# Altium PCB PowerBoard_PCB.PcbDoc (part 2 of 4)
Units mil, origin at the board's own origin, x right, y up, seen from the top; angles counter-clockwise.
Board outline 9251.97 x 3346.46 mil, 6 copper layers (Top Layer, Signal Layer 1, Signal Layer 2, Signal Layer 3, Signal Layer 4, Bottom Layer), stack 65.8 mil thick; 241 components, 145 nets, 894 pads, 120 vias.
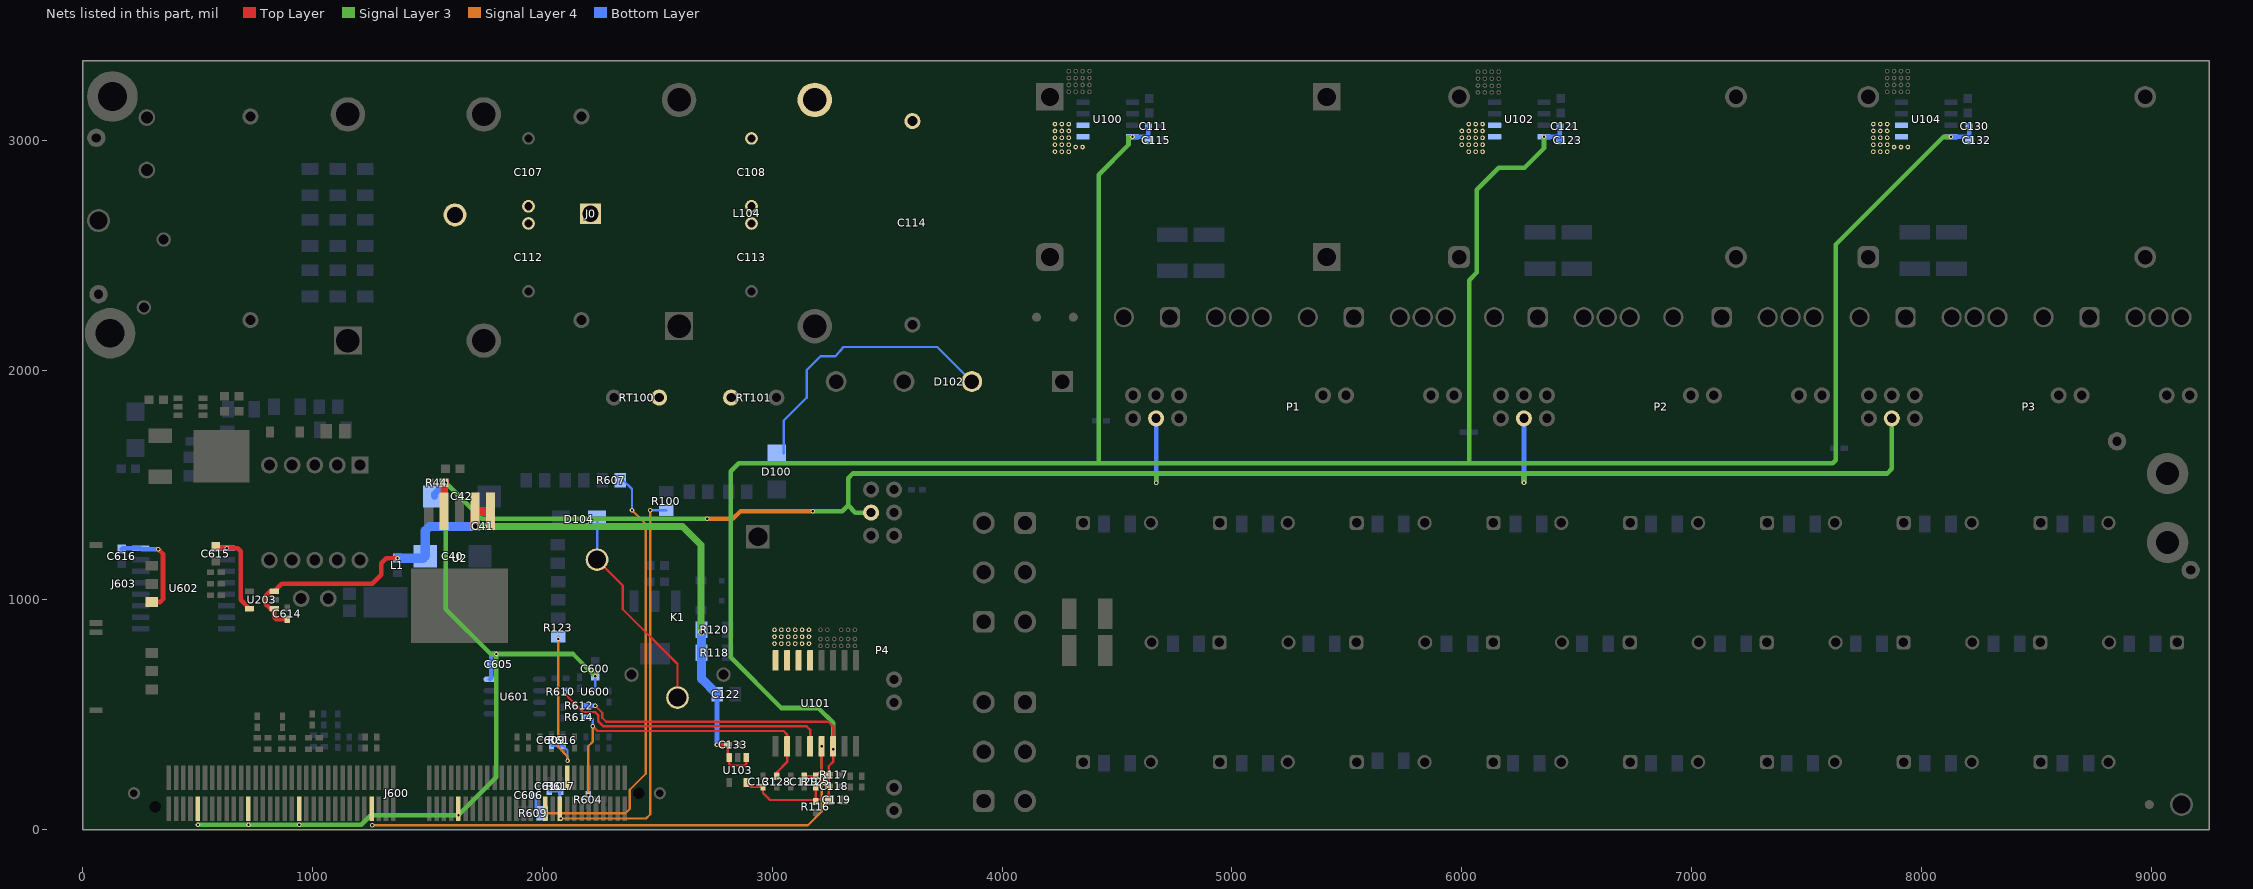
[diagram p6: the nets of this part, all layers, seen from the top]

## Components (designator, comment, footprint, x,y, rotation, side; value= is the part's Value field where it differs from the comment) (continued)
R43 "CRCW08052R70JNEA" 0805_HV 470,1580 r90 bottom value=2.7
R44 "RC0603FR-0720K5L" 0603 1540,1510 r0 top value=20.5k
R45 "RC0603FR-076K19L" 0603 1610,1570 r180 top value=6.19k
R100 "RT0805BRD07361KL" 0805_HV 2540,1430 r90 bottom value=361k
R101 "RT0805BRD07361KL" 0805_HV 2680,1470 r0 bottom value=361k
R102 "RT0805BRD07361KL" 0805_HV 2850,1470 r0 bottom value=361k
R105 "CRCW1206330KJNEA" 1206 1230,2817.09 r90 bottom value=330k
R106 "CRCW1206330KJNEA" 1206 1110,2817.09 r90 bottom value=330k
R107 "CRCW1206330KJNEA" 1206 990,2817.09 r90 bottom value=330k
R108 "CRCW1206330KJNEA" 1206 1230,2597.09 r90 bottom value=330k
R109 "CRCW1206330KJNEA" 1206 1110,2597.09 r90 bottom value=330k
R110 "CRCW1206330KJNEA" 1206 990,2597.09 r90 bottom value=330k
R111 "CRCW1206330KJNEA" 1206 1230,2377.09 r90 bottom value=330k
R112 "CRCW1206330KJNEA" 1206 1110,2377.09 r90 bottom value=330k
R113 "CRCW1206330KJNEA" 1206 990,2377.09 r90 bottom value=330k
R116 "CRCW040210K0FKED" 0402 3190,100 r90 top value=10.0k
R117 "CRCW040212K7FKED" 0402 3270,240 r0 top value=12.7k
R118 "CRCW12066R20JNEA" 1206 2750,770 r180 bottom value=6.2
R119 "RT0805BRD07361KL" 0805_HV 2066.61,1200 r90 bottom value=361k
R120 "CRCW12066R20JNEA" 1206 2750,870 r180 bottom value=6.2
R121 "RT0805BRD07361KL" 0805_HV 2070.05,1040 r90 bottom value=361k
R122 "RC0603FR-0710KL" 0603 2500,1150 r180 bottom value=10.0k
R123 "RT0805BRD07361KL" 0805_HV 2070,880 r90 bottom value=361k
R124 "CRCW04025K49FKED" 0402 3340,210 r90 top value=5.49k
R125 "CRCW0402330KJNED" 0402 3190,210 r90 top value=330k
R600 "CRCW04021K40FKED" 0402 2090,378.19 r270 top value=1.40k
R601 "CRCW04022K00FKED" 0402 2161.82,640 r270 bottom value=2.00k
R602 "RT0805BRD07361KL" 0805_HV 1970,1520 r180 bottom value=361k
R603 "CRCW04021K40FKED" 0402 2040,378.19 r270 top value=1.40k
R604 "CRCW040210K0JNED" 0402 2200,130 r90 bottom value=10k
R605 "RT0805BRD07361KL" 0805_HV 2140,1520 r0 bottom value=361k
R606 "CRCW04023K92FKED" 0402 2080,660 r0 bottom value=1.8k
R607 "RT0805BRD07361KL" 0805_HV 2300,1520 r0 bottom value=361k
R608 "CRCW04021K40FKED" 0402 1890,380 r270 top value=1.40k
R609 "CRCW08055K49FKEA" 0805_HV 1960,71.58 r0 bottom value=5.49k
R610 "CRCW04021K00FKED" 0402 2080,600 r180 bottom value=1.00k
R611 "RC0402FR-0733RL" 0402 2190,380 r90 bottom value=33.0
R612 "CRCW040210K0FKED" 0402 2161.82,540 r0 bottom value=10.0k
R613 "ERA-2AEB4871X" 0402 2240,380 r270 bottom value=4.87k
R614 "CRCW04020000Z0ED" 0402 2161.82,490 r0 bottom value=0
R615 "CRCW040210K0FKED" 0402 2090,510 r90 bottom value=10.0k
R616 "CRCW04025K23FKED" 0402 2090,390 r270 bottom value=5.23k
R617 "CRCW04025K23FKED" 0402 2080,190 r270 bottom value=5.23k
R618 "CRCW04024K99FKED" 0402 1000,480 r90 top value=4.99k
R620 "CRCW04024K99FKED" 0402 870,470 r90 top value=4.99k
R621 "CRCW04020000Z0ED" 0402 4430,1780 r180 bottom value=0
R624 "CRCW04024K99FKED" 0402 760,470 r90 top value=4.99k
R625 "CRCW04020000Z0ED" 0402 6030,1730 r180 bottom value=0
R626 "CRCW04020000Z0ED" 0402 7640,1660 r180 bottom value=0
R630 "CRCW04021K40FKED" 0402 1280,380 r270 top value=1.40k
R631 "CRCW04029K31FKED" 0402 1006.35,400 r0 top value=9.31k
R632 "CRCW04029K31FKED" 0402 890,350 r0 top value=9.31k
R633 "CRCW04029K31FKED" 0402 783.62,400 r180 top value=9.31k
R634 "CRCW04020000Z0ED" 0402 3630,1480 r0 bottom value=0
R635 "CRCW04024K99FKED" 0402 1050,480 r90 bottom value=4.99k
R636 "CRCW04029K31FKED" 0402 1028,411.65 r0 bottom value=9.31k
R640 "CRCW04020000Z0ED" 0402 1110,381.65 r270 bottom value=0
R641 "CRCW04020000Z0ED" 0402 1160,380 r270 bottom value=0
R642 "CRCW04020000Z0ED" 0402 1210,380 r90 bottom value=0
R643 "CRCW04020000Z0ED" 0402 1110,480 r270 bottom value=0
R644 "CRCW04020000Z0ED" 0402 580,1120 r0 top value=0
R645 "CRCW04020000Z0ED" 0402 580,1070 r0 top value=0
R646 "CRCW04020000Z0ED" 0402 580,1020 r0 top value=0
RT100 "B59751B0120A070" TDK_B751 2410,1880 r90 top value=50
RT101 "B59751B0120A070" TDK_B751 2920,1880 r270 top value=50
RV100 "S10K275E2" VAR_S10K275E2 310,2420 r90 top
T1 "7508110162" WURTH_7508110162 1010,1380 r270 top
TP100 "5000" Keystone5000 8850,1690 r90 top value=Red
TP101 "5000" Keystone5000 60,3010 r90 top value=Red
TP102 "5001" Keystone5001 9170,1130 r90 top value=Black
TP103 "5001" Keystone5001 70,2330 r90 top value=Black
U1 "UCC28700QDBVRQ1" DBV0006A_N 470,1840 r0 top
U2 "TL1963AQKTTRQ1" KTT0005A_N 1640,1140 r270 top
U100 "ACS722LLCTR-20AB-T" SOIC-8 4460,3090 r0 bottom
U101 "ACS716KLATR-25CB-NL-T" SOIC-16 3190,550 r270 top
U102 "ACS722LLCTR-20AB-T" SOIC-8 6250,3090 r0 bottom
U103 "TLV71333PQDBVRQ1" DBV0005A_N 2850,260 r270 top
U104 "ACS722LLCTR-20AB-T" SOIC-8 8020,3090 r0 bottom
U203 "TLV71333PQDBVRQ1" DBV0005A_N 780,1000 r180 top
U600 "SN74LVC1G3157DRYR" DRY0006A 2230,600 r90 bottom
U601 "OPA2376AIDG4" D0008A_N 1880,580 r180 bottom
U602 "ISO7831DWR" DW0016B_N 440,1050 r180 bottom

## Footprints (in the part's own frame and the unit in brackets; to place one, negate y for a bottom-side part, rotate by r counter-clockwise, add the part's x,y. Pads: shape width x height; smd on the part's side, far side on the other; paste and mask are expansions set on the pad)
0402 [mm] "0402 from SM-752 data"
  rect 0.8x0.6 smd: 1(-0.6,0) 2(0.6,0)
  silkscreen extent -1.22,-0.52 1.22,0.52, body extent -0.55,-0.3 0.55,0.3, height 0.6
0603 [mm] "0603 from SM-752 data"
  rect 1x0.95 smd: 1(-0.8,0) 2(0.8,0)
  silkscreen extent -1.52,-0.69 1.52,0.69, body extent -0.87,-0.47 0.87,0.47, height 1
0805_HV [mil] "0805 with 30mil clearance between pads"
  rect 50x63 smd: 1(-40,0) 2(40,0)
  silkscreen extent -74,-40 74,40, body extent -43,-29 43,29, height 57
1206 [mm] "1206 from SM-752 data"
  rect 1.3x1.85 smd: 1(-1.45,0) 2(1.45,0)
  silkscreen extent -2.4,-1.21 2.4,1.21, body extent -1.7,-0.9 1.7,0.9, height 1.35
1206_180 [mm] "1206_180"
  rect 1.1x1.6 smd: 1(-1.7,0) 2(1.7,0)
  silkscreen extent -0.9,-1 0.9,1, body extent -1.75,-0.95 1.75,0.95, height 1.8
1812 [mm]
  rect 1.6x3.4 smd: 1(-2,0) 2(2,0)
  silkscreen extent -0.8,-1.6 0.8,1.6, body extent -2.4,-1.7 2.4,1.7, height 1.35
7343-30 [mm] "Medium Density based on Kemet T495 dimensions"
  rect 2.55x2.45 smd: 1(-3.025,0) 2(3.025,0)
  silkscreen extent -3.8,-2.25 3.8,2.25, body extent -3.8,-2.3 3.8,2.3, height 3.1
BXW_1450x4500 [mm] "TH, 2-Leads, Dia 14.5mm, Pin Spacing 7.5mm"
  rrect50% 1.575x1.575 hole 1.05: 1(-3.75,0)
  round 1.575 hole 1.05: 2(3.75,0)
  silkscreen extent -7.5,-7.5 7.5,7.5, body extent -7.5,-7.49 7.51,7.49, height 47
controlCARD-120HSEC [mm] "Pads are not numbered according to Samtec datasheet."
  rect 0.5x2.724 smd: 1(-23.357,-1.678) 2(-23.357,1.722) 3(-22.557,-1.678) 4(-22.557,1.722) 5(-21.757,-1.678) 6(-21.757,1.722) 7(-20.957,-1.678) 8(-20.957,1.722) 9(-20.157,-1.678) 10(-20.157,1.722) 11(-19.357,-1.678) 12(-19.357,1.722) 13(-18.557,-1.678) 14(-18.557,1.722) 15(-17.757,-1.678) 16(-17.757,1.722) 17(-16.957,-1.678) 18(-16.957,1.722) 19(-16.157,-1.678) 20(-16.157,1.722) 21(-15.357,-1.678) 22(-15.357,1.722) 23(-14.557,-1.678) 24(-14.557,1.722) 25(-13.757,-1.678) 26(-13.757,1.722) 27(-12.957,-1.678) 28(-12.957,1.722) 29(-12.157,-1.678) 30(-12.157,1.722) 31(-11.357,-1.678) 32(-11.357,1.722) 33(-10.557,-1.678) 34(-10.557,1.722) 35(-9.757,-1.678) 36(-9.757,1.722) 37(-8.957,-1.678) 38(-8.957,1.722) 39(-8.157,-1.678) 40(-8.157,1.722) 41(-7.357,-1.678) 42(-7.357,1.722) 43(-6.557,-1.678) 44(-6.557,1.722) 45(-5.757,-1.678) 46(-5.757,1.722) 47(-4.957,-1.678) 48(-4.957,1.722) 49(-4.157,-1.678) 50(-4.157,1.722) 51(-3.357,-1.678) 52(-3.357,1.722) 53(-2.557,-1.678) 54(-2.557,1.722) 55(-1.757,-1.678) 56(-1.757,1.722) 57(2.243,-1.678) 58(2.243,1.722) 59(3.043,-1.678) 60(3.043,1.722) 61(3.843,-1.678) 62(3.843,1.722) 63(4.643,-1.678) 64(4.643,1.722) 65(5.443,-1.678) 66(5.443,1.722) 67(6.243,-1.678) 68(6.243,1.722) 69(7.043,-1.678) 70(7.043,1.722) 71(7.843,-1.678) 72(7.843,1.722) 73(8.643,-1.678) 74(8.643,1.722) 75(9.443,-1.678) 76(9.443,1.722) 77(10.243,-1.678) 78(10.243,1.722) 79(11.043,-1.678) 80(11.043,1.722) 81(11.843,-1.678) 82(11.843,1.722) 83(12.643,-1.678) 84(12.643,1.722) 85(13.443,-1.678) 86(13.443,1.722) 87(14.243,-1.678) 88(14.243,1.722) 89(15.043,-1.678) 90(15.043,1.722) 91(15.843,-1.678) 92(15.843,1.722) 93(16.643,-1.678) 94(16.643,1.722) 95(17.443,-1.678) 96(17.443,1.722) 97(18.243,-1.678) 98(18.243,1.722) 99(19.043,-1.678) 100(19.043,1.722) 101(19.843,-1.678) 102(19.843,1.722) 103(20.643,-1.678) 104(20.643,1.722) 105(21.443,-1.678) 106(21.443,1.722) 107(22.243,-1.678) 108(22.243,1.722) 109(23.043,-1.678) 110(23.043,1.722) 111(23.843,-1.678) 112(23.843,1.722) 113(24.643,-1.678) 114(24.643,1.722) 115(25.443,-1.678) 116(25.443,1.722) 117(26.243,-1.678) 118(26.243,1.722) 119(27.043,-1.678) 120(27.043,1.722)
  round 0.025 hole 1.27 unplated mask+0.876: 181(-24.857,0.022) 182(28.543,1.522)
  round 1.348 hole 0.84: 185(-27.207,0.022) 186(30.893,0.022)
  silkscreen extent -32.11,-3.86 35.8,3.9, body extent -31.75,-3.48 35.3,3.52, height 12.35
D0008A_N [mm] "SOIC, 8-Leads, Body 4.9x3.9mm, Pitch 1.27mm, IPC Medium Density"
  oval 1.45x0.6 smd: 1(-2.725,1.905) 2(-2.725,0.635) 3(-2.725,-0.635) 4(-2.725,-1.905) 5(2.725,-1.905) 6(2.725,-0.635) 7(2.725,0.635) 8(2.725,1.905)
  silkscreen extent -3.3,-2.5 0.9,2.5, body extent -3,-2.45 3,2.45, height 1.63
DBV0005A_N [mm] "SOT23, 5-Leads, Body 2.9x1.6mm, Pitch 0.95mm, Lead Span 2.8mm, IPC Medium Density"
  rrect17% 1x0.6 smd: 1(-1.375,0.95) 2(-1.375,0) 3(-1.375,-0.95) 4(1.375,-0.95) 5(1.375,0.95)
  silkscreen extent -1.63,-1.55 0.38,1.55, body extent -1.42,-1.46 1.42,1.46, height 1.09
DBV0006A_N [mm] "SOT23, 6-Leads, Body 2.9x1.6mm, Pitch 0.95mm, Lead Span 2.8mm, IPC Medium Density"
  rrect17% 1x0.6 smd: 1(-1.375,0.95) 2(-1.375,0) 3(-1.375,-0.95) 4(1.375,-0.95) 5(1.375,0) 6(1.375,0.95)
  silkscreen extent -1.68,-1.55 0.5,1.55, body extent -1.42,-1.46 1.42,1.46, height 1.12
DPAK [mm] "D-PAK, 3-Pads, Body 6.22x6.73mm (max), TO-252AA using nominal STEP model"
  rrect6% 2.6x1.6 smd: 1(-3.4,2.28) 3(-3.4,-2.28)
  rrect2% 6.2x5.8 smd paste-2.9: 4(3.4,0)
  silkscreen extent -4.5,-3.3 4.7,3.28, body extent -3.86,-3.29 5.84,3.29, height 2.48
Driver [mil]
  round 70 hole 40: 1(-200,-100) 2(-100,-100) 3(0,-100) 4(-200,0) 5(-100,0) 6(0,0) 7(626,0) 8(726,0) 9(1096,0) 10(1196,0)
  silkscreen extent -305,-250 1280,248, body extent -299,-249 1276,244, height 1600
DRY0006A [mm] "PSON, 6-Leads, Body 1x1.45mm, Pitch 0.5mm, TI Recommended"
  rect 0.35x0.2 smd: 1(-0.275,0.5)
  rect 0.3x0.2 smd: 2(-0.3,0) 3(-0.3,-0.5) 4(0.3,-0.5) 5(0.3,0) 6(0.3,0.5)
  silkscreen extent -0.5,-0.85 0.2,0.85, body extent -0.53,-0.75 0.53,0.75, height 0.61
DW0016B_N [mm] "SOIC, 16-Leads, Body 10.5x7.6mm, Pitch 1.27mm, IPC Medium Density"
  rrect17% 1.9x0.6 smd: 1(-4.75,4.445) 2(-4.75,3.175) 3(-4.75,1.905) 4(-4.75,0.635) 5(-4.75,-0.635) 6(-4.75,-1.905) 7(-4.75,-3.175) 8(-4.75,-4.445) 9(4.75,-4.445) 10(4.75,-3.175) 11(4.75,-1.905) 12(4.75,-0.635) 13(4.75,0.635) 14(4.75,1.905) 15(4.75,3.175) 16(4.75,4.445)
  silkscreen extent -5.6,-5.25 3.4,5.25, body extent -5.17,-5.15 5.17,5.15, height 2.59
E_900x700x900 [mm] "TH, 2- Leads, Body 9x7mm, Pin Spacing 7.5mm"
  round 1.4 hole 0.9: 1(-3.75,0) 2(3.75,0)
  silkscreen extent -4.5,-3.5 4.5,3.5, body extent -4.5,-3.5 4.5,3.5, height 12
Fiducial10-20 [mm]
  round 1 smd mask+0.5: 1(0,0)
  Top Layer keep-out circle w1.178: c0,0 r0.5
FUSE_0325_Vertical [mm] "TH, 2-Leads, Dia 6.985mm, Verical, Pin Spacing 5.8025mm"
  round 1.85 hole 1.35: 1(0,0) 2(-5.803,0)
  silkscreen extent -3.64,-3.64 3.64,3.64, body extent -6.34,-3.64 3.64,3.64, height 37.62
G184014LF#1 [mm] "TH, 4-Leads, Dia 42.5mm"
  rrect50% 3.048x3.048 hole 2: 1(-8.85,15.3)
  rect 3.048x3.048 hole 2: 2(8.85,15.3) 3(8.85,-15.3) 4(-8.85,-15.3)
  body extent -11.8,-21.25 11.84,21.25, height 44.5
G184014LF#2 [mm] "TH, 4-Leads, Dia 42.5mm"
  rrect50% 2.4x2.4 hole 1.6: 1(-8.85,15.3)
  round 2.4 hole 1.6: 2(8.85,15.3) 3(8.85,-15.3) 4(-8.85,-15.3)
  body extent -11.8,-21.25 11.84,21.25, height 44.5
GBJ [mm] "Micro Commercial Components"
  rect 2.3x2.3 hole 1.6: 1(-12.5,0)
  round 2.3 hole 1.6: 2(-2.5,0) 3(5,0) 4(12.5,0)
  silkscreen extent -15.3,-1.8 15,3.1, body extent -15.25,-1.75 15.05,3.05, height 24.3
Hirose_DF59-3S-2V_51 [mm] "Receptacle, 2mm, 3x1, SMT"
  rect 1.1x1.4 smd: 1(-2,7.9) 2(0,7.9) 3(2,7.9)
  rect 0.65x1.4 smd: MP1(-4.31,1.75) MP2(4.31,1.75)
  silkscreen extent -4.6,2.75 4.6,8.25, body extent -4.6,0.35 4.6,8.3, height 2.3
IEC_HighVoltage_Small [mil]
  silkscreen extent -107,-88 107,97
Keystone5000 [mil] "For Keystone 500x miniature loop terminals"
  round 80 hole 40: 1(0,0)
  silkscreen extent -52,-52 52,52, body extent -49,-49 49,49, height 182
Keystone5001 [mil] "For Keystone 500x miniature loop terminals"
  round 80 hole 40: 1(0,0)
  silkscreen extent -52,-52 52,52, body extent -49,-49 49,49, height 182
KTT0005A_N [mm] "D2-PAK, 6-Leads, Body 8.9x10.2mm, Pitch 1.7mm, Lead Span 15.2mm, IPC Medium Density"
  rrect10% 4.15x1 smd: 1(-6.25,3.4) 2(-6.25,1.7) 3(-6.25,0) 4(-6.25,-1.7) 5(-6.25,-3.4)
  rrect1% 8.2x10.75 smd: 6(4.2,0)
  silkscreen extent -6.42,-5.35 -0.3,5.35, body extent -7.63,-5.08 7.63,5.08, height 4.83
Pb-Free_Overlay_Small [mil]
  silkscreen extent -46,-46 46,46
PIN1 [mil] "Connector; Plug"
  rect 90x90 hole 70: 1(0,0)
  silkscreen extent -55,-55 55,86
POWERDI5 [mm] "Diodes Inc recommended land pattern, ap02001.pdf rev 60"
  rect 1.4x1.39 smd: 1(-1.991,0.92) 2(-1.991,-0.92)
  rect 4.86x3.36 smd: 3(1.991,0)
  silkscreen extent -1.7,-2.1 3.8,2.1, body extent -2.27,-2.02 4.33,2.03, height 1.17
Relay_T90S1 [mm] "TH, 5-Leads, Body 27.43x32.26mm"
  rect 2.6x2.6 hole 2.06: 1(8.335,5.97)
  round 2.5 hole 1.98: 2(-9.445,3.43) 3(-0.555,-11.81)
  round 1.6 hole 1.09: 4(-5.635,-9.27) 5(4.525,-9.27)
  silkscreen extent -13.71,-16.13 14.53,16.13, body extent -13.71,-16.13 13.71,16.13, height 20.4
SMA [mm] "Molded Diode, 2-Leads, Body 4.3x2.6mm, IPC Medium Density, based on OnSemi component dimensions and land pattern"
  rect 2x2 smd: 1(-2,0) 2(2,0)
  silkscreen extent -3.66,-1.57 2.79,1.57, body extent -2.6,-1.3 2.6,1.3, height 2.42
SOD-123 [mm] "On Semi recommended land pattern"
  rect 0.915x1.22 smd: 1(-1.637,0) 2(1.637,0)
  silkscreen extent -2.74,-1.17 2.03,1.17, body extent -1.93,-0.9 1.93,0.9, height 1.35
SOD-323 [mm] "NXP recommended land pattern"
  rect 0.6x0.6 smd paste-0.05: 1(-1.1,0) 2(1.1,0)
  silkscreen extent -2.06,-0.86 1.53,0.86, body extent -1.3,-0.67 1.3,0.68, height 1.1
SOIC-8 [mm] "duplicate of SO-8.  SOIC, 8-Leads, Body 5.0x4.0mm (max), Pitch 1.27mm, IPC Medium Density"
  rrect17% 1.45x0.6 smd: 1(-2.725,1.905) 2(-2.725,0.635) 3(-2.725,-0.635) 4(-2.725,-1.905) 5(2.725,-1.905) 6(2.725,-0.635) 7(2.725,0.635) 8(2.725,1.905)
  silkscreen extent -3.5,-2.5 0.9,2.5, body extent -3,-2.45 3,2.45, height 1.63
SOIC-16 [mm] "SOIC, 16-Leads, Body 10.3x7.5mm, Pitch 1.27mm"
  rrect15% 2.25x0.65 smd: 1(-4.75,4.445) 2(-4.75,3.175) 3(-4.75,1.905) 4(-4.75,0.635) 5(-4.75,-0.635) 6(-4.75,-1.905) 7(-4.75,-3.175) 8(-4.75,-4.445) 9(4.75,-4.445) 10(4.75,-3.175) 11(4.75,-1.905) 12(4.75,-0.635) 13(4.75,0.635) 14(4.75,1.905) 15(4.75,3.175) 16(4.75,4.445)
  silkscreen extent -4.87,-5.25 3.8,5.45, body extent -5.32,-5.25 5.32,5.25, height 2.64
SOT-223 [mm] "SOT223/SC73, 4-Leads, Body 6.5x3.5mm, Pitch 2.3mm, Lead Span 7mm, IPC Medium Density"
  rrect10% 2.4x1 smd: 1(-2.9,2.3) 2(-2.9,0) 3(-2.9,-2.3)
  rrect4% 2.4x3.3 smd: 4(2.9,0)
  silkscreen extent -3.32,-3.35 1.4,3.35, body extent -3.5,-3.25 3.5,3.25, height 1.62
TDK_B751 [mil] "TH, 2-Leads, Dia 12.5mm, Pin Spacing 5mm"
  round 70 hole 40: 1(0,98.43) 2(0,-98.43)
  silkscreen extent -138,-246 138,246, body extent -137,-244 137,246, height 649
TO-247 [mil] "Standard TO-247"
  rrect50% 95x95 hole 62: 1(-215,0)
  round 95 / inner round 74.8 / far side round 96 hole 62: 2(0,0) 3(215,0)
  silkscreen extent -318,-124 318,81, body extent -318,-124 318,81, height 1007
TO-247-4 [mm] "FM, 4-Leads, Body 15.94x5.02mm, Pitch 2.54mm"
  rrect50% 2.24x2.24 hole 1.7: 1(-5.08,0)
  round 2.24 hole 1.7: 2(0,0) 3(2.54,0) 4(5.08,0)
  silkscreen extent -8.07,-2.49 8.07,2.72, body extent -8.07,-2.49 8.07,2.72, height 27.97
VAR_S10K275E2 [mm] "EPCOS"
  round 1.6 hole 1.1: 1(-3.75,1.1) 2(3.75,-1.1)
  silkscreen extent -6,-2.7 6,2.7, body extent -5.98,-2.7 5.98,2.7, height 14.99
WCAP-FTX2_2600x1500x2500 [mil] "TH, 2-Leads, Body 26x15mm, Pin Spacing 22.5mm"
  round 70 hole 43.31: 1(-442.91,0) 2(442.91,0)
  silkscreen extent -512,-295 512,295, body extent -512,-295 512,295, height 984
WE-CMBNC_XL [mm] "TH, 4-Leads, Body 37x23mm"
  rect 3.1x3.1 hole 2.6: 1(-7.5,-12.5)
  round 3.81 hole 2.6: 2(-7.5,12.5) 3(7.5,12.5) 4(7.5,-12.5)
  silkscreen extent -10.3,-16.17 10.3,16.17, body extent -10.3,-16.17 10.3,16.17, height 30.09
WURTH_7508110162 [mm] "WURTH"
  rect 1.85x1.85 hole 1.191: 1(-5.25,5)
  round 1.85 hole 1.191: 2(-5.25,2.5) 3(-5.25,0) 4(-5.25,-2.5) 5(-5.25,-5) 6(5.25,-5) 7(5.25,-2.5) 8(5.25,0) 9(5.25,2.5) 10(5.25,5) A(9.5,1.5) B(9.5,-1.5)
  silkscreen extent -7,-6.8 7,7, body extent -6.98,-6.95 7.04,6.85, height 7

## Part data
C1 C2 C3 C4 C5 C6 C7 C8 C9 C10 C11 C12 C13 C14 C15 C16 C17 C18 C19 C20 C21 C22 C23 C24: library part CMP-0077904-1, "CAP, AL, 150 µF, 350 V, +/- 20%, TH", Cap_Case=14.5x45mm, Manufacturer=Rubycon, Supplier Part Number 1=93Y0837, Tolerance_%=20%, Value2=350V, ValueDisplayed=150µF
C27 C28 C29 C30 C31 C32 C33 C34: "CAP, CERM, 0.1µF, 1kV,+/- 10%, X7R, 1812", Cap_Case=1812, Manufacturer=KEMET, PartNumber=C1812C104KDRAC7800, TempCo=X7R, Tolerance_%=10, Value2=1000V, ValueDisplayed=0.1µF
C35: "CAP, CERM, 10 µF, 25 V,+/- 10%, X7R, 1206", Cap_Case=1206, Manufacturer=MuRata, Supplier Part Number 1=81-GRM31CR71E106KA12, TempCo=X7R, Tolerance_%=10, Value2=25V, ValueDisplayed=10µF
C36: library part CMP-0064943-2, "CAP, CERM, 1000 pF, 250 V,+/- 10%, X7R, 0805", Cap_Case=0805, Manufacturer=TDK, Supplier Part Number 1=445-2277-1-ND, TempCo=X7R, Tolerance_%=10%, Value1=Unknown, Value2=250V, ValueDisplayed=1000pF
C37: "CAP, CERM, 68pF, 50V, +/-5%, C0G/NP0, 0603", Cap_Case=0603, Manufacturer=AVX, Supplier Part Number 1=478-1173-1-ND, TempCo=C0G/NP0, Tolerance_%=5, Value1="0.144 ohm", Value2=50V, ValueDisplayed=68pF
C38 C41 C115 C119 C123 C132: "CAP, CERM, 1uF, 6.3V, +/-10%, X5R, 0603", Cap_Case=0603, Manufacturer=MuRata, Supplier Part Number 1=81-GRM185R60J105KE26, TempCo=X5R, Tolerance_%=10, Value1=Unknown, Value2=6.3V, ValueDisplayed=1µF
C39 C40 C42: "CAP, Tantalum Polymer, 220 µF, 10 V,+/- 20%, 0.025 ohm, 7343-30 SMD", Cap_Case=7343-30, Manufacturer=Panasonic, Supplier Part Number 1=P16451CT-ND, Tolerance_%=20, Value1="0.025 ohm", Value2=10V, ValueDisplayed=220µF
C107 C108 C112 C113: "CAP, CERM, 2200 pF, 300 V, +/- 20%, E, TH, 2- Leads, Body 9x7mm, Pin Spacing 7.5mm", Cap_Case=9x7x9mm, Manufacturer=MuRata, Supplier Part Number 1=DE6E3KJ222MN3A-ND, TempCo=E, Tolerance_%=20, Value1=Unknown, Value2=300V, ValueDisplayed=2200pF
C109 C110 C114: "CAP, Film, 2.2 µF, 275 V, +/- 10%, TH", Cap_Case=26x15x25mm, Manufacturer="Wurth Elektronik", Supplier Part Number 1=732-5914-ND, Tolerance_%=10, Value1=Unknown, Value2=275V, ValueDisplayed=2.2µF
C111 C118 C121 C124 C130 C131 C133 C614: "CAP, CERM, 0.1uF, 6.3V, +/-10%, X7R, 0402", Cap_Case=0402, Manufacturer=MuRata, Supplier Part Number 1=GRM155R70J104KA01D-ND, TempCo=X7R, Tolerance_%=10, Value1=Unknown, Value2=6.3V, ValueDisplayed=0.1uF
C116 C125 C134: "CAP, CERM, 1000 pF, 50 V, +/- 10%, C0G/NP0, 0603", Cap_Case=0603, Manufacturer=AVX, Supplier Part Number 1=478-3718-1-ND, TempCo=C0G/NP0, Tolerance_%=10, Value1="0.048 ohm", Value2=50V, ValueDisplayed=1000pF
C120: "CAP, CERM, 1000pF, 16V, +/-10%, X7R, 0603", Cap_Case=0603, Manufacturer=MuRata, Supplier Part Number 1=GRM188R71C102KA01D-ND, TempCo=X7R, Tolerance_%=10, Value1=Unknown, Value2=16V, ValueDisplayed=1000pF
C122: "CAP, CERM, 10 µF, 16 V,+/- 10%, X5R, 0805", Cap_Case=0805, Manufacturer=AVX, Supplier Part Number 1=478-5165-1-ND, TempCo=X5R, Tolerance_%=10, Value2=16V, ValueDisplayed=10µF
C127 C128: "CAP, CERM, 1000pF, 6.3V, +/-10%, X5R, 0402", Cap_Case=0402, Manufacturer=MuRata, Supplier Part Number 1=GRM155R60J102KA01D-ND, TempCo=X5R, Tolerance_%=10, Value1=Unknown, Value2=6.3V, ValueDisplayed=1000pF
C129: "CAP, CERM, 0.022uF, 6.3V, +/-10%, X7R, 0402", Cap_Case=0402, Manufacturer=MuRata, Supplier Part Number 1=GRM155R70J223KA01D-ND, TempCo=X7R, Tolerance_%=10, Value1=Unknown, Value2=6.3V, ValueDisplayed=0.022uF
C600 C605 C615 C616: "CAP, CERM, 1uF, 25V, +/-10%, X7R, 0603", Cap_Case=0603, Manufacturer=TDK, Supplier Part Number 1=445-5956-1-ND, TempCo=X7R, Tolerance_%=10, Value1=Unknown, Value2=25V, ValueDisplayed=1uF
C601 C604 C607 C611 C612 C613 C617 C618: "CAP, CERM, 0.01uF, 6.3V, +/-10%, X7R, 0402", Cap_Case=0402, Manufacturer=MuRata, Supplier Part Number 1=GRM155R70J103KA01D-ND, TempCo=X7R, Tolerance_%=10, Value1=Unknown, Value2=6.3V, ValueDisplayed=0.01uF
C602: "CAP, CERM, 0.1 µF, 16 V, +/- 10%, X7R, 0402", Cap_Case=0402, Manufacturer=MuRata, Supplier Part Number 1=490-4759-2-ND, TempCo=X7R, Tolerance_%=10, Value1=Unknown, Value2=16V, ValueDisplayed=0.1µF
C603: "CAP, CERM, 0.1uF, 6.3V, +/-10%, X5R, 0402", Cap_Case=0402, Manufacturer=MuRata, Supplier Part Number 1=GRM155R60J104KA01D-ND, TempCo=X5R, Tolerance_%=10, Value1=Unknown, Value2=6.3V, ValueDisplayed=0.1µF
C606 C609 C610: "CAP, CERM, 470 pF, 50 V,+/- 5%, C0G/NP0, 0402", Cap_Case=0402, Manufacturer=MuRata, Supplier Part Number 1=490-1297-1-ND, TempCo=C0G/NP0, Tolerance_%=5, Value2=50V, ValueDisplayed=470pF
C608: library part C1005X5R1A473K050BA, "CAP, CERM, 0.047 µF, 10 V, +/- 10%, X5R, 0402", Cap_Case=0402, Manufacturer=TDK, Supplier Part Number 1=445-4980-1-ND, TempCo=X5R, Tolerance_%=10, Value1=Unknown, Value2=10V, ValueDisplayed=0.047µF
D1: "Diode, Ultrafast, 200 V, 1 A, SMA", Manufacturer="Diodes Inc.", Supplier Part Number 1=ES1D-FDICT-ND, Value1=1A, Value2=0.92V
D2: library part US1M-13-F, "Diode, Ultrafast, 800V, 1A, SMA", Manufacturer="Diodes Inc.", Supplier Part Number 1=US1M-FDICT-ND, Value1=1A, Value2=800V
D3: library part CMP-0077048-1, "Diode, Schottky, 100 V, 5 A, PowerDI5", Manufacturer="Diodes Inc.", Supplier Part Number 1=PDS5100DICT-ND, Value1=5A, Value2=0.79V
D100 D104: "Diode, Fast Rectifier, 800 V, 1 A, SMA", Manufacturer="Diodes Inc.", Supplier Part Number 1=US1K-FDICT-ND, Value1=1A, Value2=1.7V
D102: "Diode, Switching-Bridge, 1000 V, 25 A, TH", Manufacturer="Diodes Inc.", Supplier Part Number 1=GBJ2510-FDI-ND, Value1=25A, Value2=1.05V
D105: "Diode, Zener, 5.1 V, 500 mW, SOD-123", Manufacturer="ON Semiconductor", Power_W=0.5, Supplier Part Number 1=MMSZ4689T1GOSCT-ND, Value1=0.5W
D106: "Diode, Schottky, 40 V, 0.75 A, AEC-Q101, SOD-323", Manufacturer="Infineon Technologies", Supplier Part Number 1=BAT165E6327HTSA1CT-ND, Value1=0.75A, Value2=0.74V
F100: library part CMP-0003448-2, "Fuse, 40 A, 250 VAC, 150 VDC, TH", Irating_A=40A, Manufacturer=Littelfuse, Supplier Part Number 1=F3336-ND
FID1 FID2 FID3: "Fiducial mark.  There is nothing to buy or mount.", Manufacturer=N/A
J600: library part controlCARD-120HSEC, "C2000 controlCARD-120HSEC connector, SMT", Manufacturer=Samtec
J602 J603: "Receptacle, 2mm, 3x1, Gold, Natural, SMT", Color=Natural, Current_A=3, Manufacturer="Hirose Electric Co. Ltd.", Supplier Part Number 1=H11965CT-ND, Voltage_V=230
K1: "Relay, SPST-NO (1 Form A), 30 A, 5 V, TH", Coil Current_A=0.185, Coil Power_W=0.9, Coil Resistance_ohm=27, Coil Voltage_VDC=5, Contact Rating_A=30, Manufacturer="TE Connectivity", Supplier Part Number 1=PB109-ND, Turn Off Voltage (Min)_VDC=0.5, Turn On Voltage (Max)_VDC=3.75
L1: "Ferrite Bead, 15 ohm @ 100 MHz, 1.5 A, 0603", Manufacturer=TDK, Supplier Part Number 1=445-2180-1-ND, Value1="0.05 ohm", Value2=1.5A, ValueDisplayed="15 ohm"
L100 L101 L102: library part CMP-0082528-1, "Inductor, Toroid, 260 µH, 0.038 ohm, TH", Manufacturer="GCI Technologies", Value1="0.038 ohm", Value2=A, ValueDisplayed=260µH
L103 L104: "CMC 2.5MH 25A 2LN TH", Manufacturer="Wurth Elektronik", PartNumber=7448052502, Supplier Part Number 1=732-5600-ND, ValueDisplayed=2.5mH
Logo3: library part Pb-Free
LOGO4: library part IEC_HighVoltage, "IEC 61010-1 High Voltage Warning"
P1 P2 P3 P4: library part "Header 10", "Connectors for driver daughter card (include one PPPC032LFBN-RC and two PPPC021LFBN-RC)", Manufacturer="Sullins Connector Solutions", PartNumber="Connectors for TIDA-01605"
Q1 Q2 Q3 Q4 Q5 Q6: library part CMP-0067575-2, "MOSFET, N-CH, 1000 V, 35 A, TO-247-4", Alternate Manufacturer=None, Manufacturer=Cree, Supplier Part Number 1=C3M0065100K-ND, Value1="? ohm", Value2="35 nC"
Q7 Q8 Q9 Q10: library part IPW60R045CP, "MOSFET, N-CH, 1200 V, 90 A, TO-247", Alternate Manufacturer=None, Manufacturer=Cree, Supplier Part Number 1=C2M0025120D-ND
Q11: library part CMP-0077905-1, "MOSFET, N-CH, 1000 V, 1.85 A, DPAK", Alternate Manufacturer=None, Manufacturer=STMicroelectronics, Supplier Part Number 1=497-7964-1-ND, Value1="? ohm", Value2="16 nC"
Q12: "MOSFET, N-CH, 70 V, 3.8 A, AEC-Q101, SOT-223", Alternate Manufacturer=None, Manufacturer="Diodes Inc.", Supplier Part Number 1=ZXMN7A11GCT-ND, Value1="0.19 ohm", Value2="7.4 nC"
R1 R2 R3 R4 R5 R6 R7 R8 R9 R10 R11 R12 R13 R14 R15 R16 R17 R18 R19 R20 R21 R22 R23 R24: "RES, 1.00 M, 1%, 0.25 W, 1206", Manufacturer=Vishay-Dale, Power_W=0.25, Supplier Part Number 1=541-1.00MFCT-ND, TempCo="100 ppm/C", Tolerance_%=1, Value1=1%, Value2=0.25W, Value_Code=1M00, ValueDisplayed=1.00M
R25: "RES, 10.0 k, 1%, 0.1 W, 0603", Manufacturer=Vishay-Dale, Power_W=0.1, Supplier Part Number 1=541-10.0KHCT-ND, TempCo="100 ppm/C", Tolerance_%=1, Value1=1%, Value2=0.1W, Value_Code=10k0, ValueDisplayed=10.0k
R35: "RES, 80.6 k, 1%, 0.1 W, 0603", Manufacturer=Vishay-Dale, Power_W=0.1, Supplier Part Number 1=541-80.6KHCT-ND, TempCo="100 ppm/C", Tolerance_%=1, Value1=1%, Value2=0.1W, Value_Code=80k6, ValueDisplayed=80.6k
R36: "RES, 28.0 k, 1%, 0.1 W, 0603", Manufacturer=Vishay-Dale, Power_W=0.1, Supplier Part Number 1=541-28.0KHCT-ND, TempCo="100 ppm/C", Tolerance_%=1, Value1=1%, Value2=0.1W, Value_Code=28k0, ValueDisplayed=28.0k
R37: "RES, 20.0, 1%, 0.1 W, 0603", Manufacturer="Yageo America", Power_W=0.1, Supplier Part Number 1=311-20.0HRCT-ND, TempCo="200 ppm/C", Tolerance_%=1, Value1=1%, Value2=0.1W, Value_Code=20R0, ValueDisplayed=20.0
R38 R39: "RES, 2.0 M, 5%, 0.25 W, 1206", Manufacturer=Vishay-Dale, Power_W=0.25, Supplier Part Number 1=541-2.0MECT-ND, TempCo="200 ppm/C", Tolerance_%=5, Value1=5%, Value2=0.25W, Value_Code=2M00, ValueDisplayed=2.0M
R40: "RES, 300 k, 1%, 0.25 W, 1206", Manufacturer="Yageo America", Power_W=0.25, Supplier Part Number 1=311-300KFRCT-ND, TempCo="100 ppm/C", Tolerance_%=1, Value1=1%, Value2=0.25W, Value_Code=300k
R41: "RES, 200, 5%, 0.125 W, 0805", Manufacturer=Panasonic, Power_W=0.125, Supplier Part Number 1=P200ACT-ND, TempCo="200 ppm/C", Tolerance_%=5, Value1=5%, Value2=0.125W, Value_Code=200R, ValueDisplayed=200
R42: "RES, 1.00k ohm, 1%, 0.1W, 0603", Manufacturer=Vishay-Dale, Power_W=0.1, Supplier Part Number 1=541-1.00KHCT-ND, TempCo="100 ppm/C", Tolerance_%=1, Value1=1%, Value2=0.1W, Value_Code=1k00
R43: "RES, 2.7, 5%, 0.125 W, 0805", Manufacturer=Vishay-Dale, Power_W=0.125, Supplier Part Number 1=541-2.7ACT-ND, TempCo="200 ppm/C", Tolerance_%=5, Value1=5%, Value2=0.125W, Value_Code=2R70, ValueDisplayed=2.7
R44: "RES, 20.5 k, 1%, 0.1 W, 0603", Manufacturer="Yageo America", Power_W=0.1, Supplier Part Number 1=311-20.5KHRCT-ND, TempCo="200 ppm/C", Tolerance_%=1, Value1=1%, Value2=0.1W, Value_Code=20k5, ValueDisplayed=20.5k
R45: "RES, 6.19 k, 1%, 0.1 W, 0603", Manufacturer="Yageo America", Power_W=0.1, Supplier Part Number 1=311-6.19KHRCT-ND, TempCo="200 ppm/C", Tolerance_%=1, Value1=1%, Value2=0.1W, Value_Code=6k19, ValueDisplayed=6.19k
R100 R101 R102 R119 R121 R123 R602 R605 R607: "RES, 361 k, 0.1%, 0.125 W, 0805", Manufacturer="Yageo America", Power_W=0.125, TempCo="25 ppm/C", Tolerance_%=0.1, Value1=0.1%, Value2=0.125W, Value_Code=361k
R105 R106 R107 R108 R109 R110 R111 R112 R113: "RES, 330 k, 5%, 0.25 W, 1206", Manufacturer=Vishay-Dale, Power_W=0.25, Supplier Part Number 1=541-330KECT-ND, TempCo="200 ppm/C", Tolerance_%=5, Value1=5%, Value2=0.25W, Value_Code=330k
R116: "RES, 10.0k ohm, 1%, 0.063W, 0402", Manufacturer=Vishay-Dale, Power_W=0.063, Supplier Part Number 1=541-10.0KLCT-ND, TempCo="100 ppm/C", Tolerance_%=1, Value1=1%, Value2=0.063W, Value_Code=10k0
R117: "RES, 12.7k ohm, 1%, 0.063W, 0402", Manufacturer=Vishay-Dale, Power_W=0.063, Supplier Part Number 1=541-12.7KLCT-ND, TempCo="100 ppm/C", Tolerance_%=1, Value1=1%, Value2=0.063W, Value_Code=12k7
R118 R120: "RES, 6.2, 5%, 0.25 W, 1206", Manufacturer=Vishay-Dale, Power_W=0.25, Supplier Part Number 1=541-6.2ECT-ND, TempCo="200 ppm/C", Tolerance_%=5, Value1=5%, Value2=0.25W, Value_Code=6R20, ValueDisplayed=6.2
R122: "RES, 10.0k ohm, 1%, 0.1W, 0603", Manufacturer="Yageo America", Power_W=0.1, Supplier Part Number 1=311-10.0KHRCT-ND, TempCo="200 ppm/C", Tolerance_%=1, Value1=1%, Value2=0.1W, Value_Code=10k0
R124: "RES, 5.49k ohm, 1%, 0.063W, 0402", Manufacturer=Vishay-Dale, Power_W=0.063, Supplier Part Number 1=541-5.49KLCT-ND, TempCo="100 ppm/C", Tolerance_%=1, Value1=1%, Value2=0.063W, Value_Code=5k49
R125: "RES, 330k ohm, 5%, 0.063W, 0402", Manufacturer=Vishay-Dale, Power_W=0.063, Supplier Part Number 1=541-330KJCT-ND, TempCo="200 ppm/C", Tolerance_%=5, Value1=5%, Value2=0.063W, Value_Code=330k
R600 R603 R608 R630: "RES, 1.40k ohm, 1%, 0.063W, 0402", Manufacturer=Vishay-Dale, Power_W=0.063, Supplier Part Number 1=541-1.40KLCT-ND, TempCo="100 ppm/C", Tolerance_%=1, Value1=1%, Value2=0.063W, Value_Code=1k40
R601: "RES, 2.00 k, 1%, 0.063 W, 0402", Manufacturer=Vishay-Dale, Power_W=0.063, Supplier Part Number 1=541-2.00KLCT-ND, TempCo="100 ppm/C", Tolerance_%=1, Value1=1%, Value2=0.063W, Value_Code=2k00, ValueDisplayed=2.00k
R604: "RES, 10k ohm, 5%, 0.063W, 0402", Manufacturer=Vishay-Dale, Power_W=0.063, Supplier Part Number 1=541-10KJCT-ND, TempCo="200 ppm/C", Tolerance_%=5, Value1=5%, Value2=0.063W, Value_Code=10k0
R606: library part CRCW04021K80JNED, "RES, 1.8 k, 5%, 0.063 W, 0402", Manufacturer=Vishay-Dale, Power_W=0.063, Supplier Part Number 1=541-1.8KJCT-ND, TempCo="200 ppm/C", Tolerance_%=5, Value1=5%, Value2=0.063W, Value_Code=1k80, ValueDisplayed=1.8k
R609: "RES, 5.49 k, 1%, 0.125 W, 0805", Manufacturer=Vishay-Dale, Power_W=0.125, Supplier Part Number 1=541-5.49KCCT-ND, TempCo="100 ppm/C", Tolerance_%=1, Value1=1%, Value2=0.125W, Value_Code=5k49, ValueDisplayed=5.49k
R610: "RES, 1.00 k, 1%, 0.063 W, 0402", Manufacturer=Vishay-Dale, Power_W=0.063, Supplier Part Number 1=541-1.00KLCT-ND, TempCo="100 ppm/C", Tolerance_%=1, Value1=1%, Value2=0.063W, Value_Code=1k00, ValueDisplayed=1.00k
R611: "RES, 33.0, 1%, 0.062 W, 0402", Manufacturer="Yageo America", Power_W=0.062, Supplier Part Number 1=311-33.0LRCT-ND, TempCo="100 ppm/C", Tolerance_%=1, Value1=1%, Value2=0.062W, Value_Code=33R0, ValueDisplayed=33.0
R612 R615: "RES, 10.0 k, 1%, 0.063 W, 0402", Manufacturer=Vishay-Dale, Power_W=0.063, Supplier Part Number 1=541-10.0KLCT-ND, TempCo="100 ppm/C", Tolerance_%=1, Value1=1%, Value2=0.063W, Value_Code=10k0, ValueDisplayed=10.0k
R613: "RES, 4.87 k, 0.1%, 0.062 W, AEC-Q200 Grade 0, 0402", Manufacturer=Panasonic, Power_W=0.062, Supplier Part Number 1=P4.87KDCCT-ND, TempCo="25 ppm/C", Tolerance_%=0.1, Value1=0.1%, Value2=0.062W, Value_Code=4k87, ValueDisplayed=4.87k
R614 R621 R625 R626 R634 R640 R641 R642 R643 R644 R645 R646: "RES, 0, 5%, 0.063 W, 0402", Manufacturer=Vishay-Dale, Power_W=0.063, Supplier Part Number 1=541-0.0JCT-ND, TempCo="200 ppm/C", Tolerance_%=5, Value1=5%, Value2=0.063W, Value_Code=0000, ValueDisplayed=0
R616 R617: "RES, 5.23 k, 1%, 0.063 W, 0402", Manufacturer=Vishay-Dale, Power_W=0.063, Supplier Part Number 1=541-5.23KLCT-ND, TempCo="100 ppm/C", Tolerance_%=1, Value1=1%, Value2=0.063W, Value_Code=5k23, ValueDisplayed=5.23k
R618 R620 R624 R635: "RES, 4.99 k, 1%, 0.063 W, 0402", Manufacturer=Vishay-Dale, Power_W=0.063, Supplier Part Number 1=541-4.99KLCT-ND, TempCo="100 ppm/C", Tolerance_%=1, Value1=1%, Value2=0.063W, Value_Code=4k99, ValueDisplayed=4.99k
R631 R632 R633 R636: "RES, 9.31 k, 1%, 0.063 W, 0402", Manufacturer=Vishay-Dale, Power_W=0.063, Supplier Part Number 1=541-9.31KLCT-ND, TempCo="100 ppm/C", Tolerance_%=1, Value1=1%, Value2=0.063W, Value_Code=9k31, ValueDisplayed=9.31k
RT100 RT101: "Thermistor NTC, 50 ohm, 25%, D12.5xH16.5mm", Manufacturer=TDK, Supplier Part Number 1=495-3880-ND, Tolerance_%=25
RV100: "Varistor 275V RMS 10MM Radial, TH", Manufacturer="EPCOS Inc", Supplier Part Number 1=495-1433-ND
T1: "Transformer, TH", Manufacturer="Wurth Elektronik"
TP100 TP101: "Test Point, Miniature, Red, TH", Manufacturer=Keystone, Supplier Part Number 1=36-5000-ND
TP102 TP103: "Test Point, Miniature, Black, TH", Manufacturer=Keystone, Supplier Part Number 1=36-5001-ND
U1: "Constant-Voltage, Constant-Current Controller With Primary-Side Regulation, DBV0006A (SOT-23-6)", Alternate Manufacturer="Texas Instruments"
U2: "Single Output Fast Transient Response LDO, 1.5 A, Adjustable 1.21 to 20 V Output, 2.1 to 20 V Input, 5-pin DDPAK (KTT), -40 to 125 degC, Green (RoHS & no Sb/Br)", Alternate Manufacturer="Texas Instruments", Alternate PartNumber=Equivalent, Supplier Part Number 1=296-27440-2-ND
U100 U102 U104: library part ACS722LLCTR-10AB-T, "High Accuracy, Galvanically Isolated Current Sensor IC, SOIC-8", Manufacturer="Allegro Microsystems Inc", Supplier Part Number 1=620-1635-1-ND
U101: library part ACS716KLATR-12CB-NL-T, "SENSOR CURRENT HALL 25A AC/DC", Manufacturer="Allegro Microsystems Inc", Supplier Part Number 1=620-1527-1-ND
U103 U203: "Capacitor-Free, 150-mA, Low-Dropout Regulator with Foldback Current Limit for Portable Devices, DBV0005A", Alternate Manufacturer="Texas Instruments"
U600: "SINGLE-POLE DOUBLE-THROW ANALOG SWITCH, DRY0006A", Alternate Manufacturer="Texas Instruments"
U601: "Precision, Low Noise, Low Quiescent Current Operational Amplifier, 2 to 5.5 V, -40 to 125 degC, 8-pin SOIC (D0008A), Green (RoHS & no Sb/Br)", Alternate Manufacturer="Texas Instruments", Alternate PartNumber=Equivalent, Supplier Part Number 1=OPA2376AIDG4-ND, Total Supply Voltage(Max)(+5V is 5, +/-5V is 10)=5.5, Total Supply Voltage(Min)(+5V is 5, +/-5V is 10)=2
U602: "High-Performance, 8000 VPK Reinforced Triple Digital Isolator, DW0016B", Alternate Manufacturer="Texas Instruments", Alternate PartNumber=ISO7831DW

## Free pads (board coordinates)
  round 100 hole 78.74: 1(70,2650) 1(9130,110)
  round 220 hole 126: 1(120,2160) 1(130,3190)
  round 20 hole 10: 1(3040,870) 1(3300,830) 1(4290,3040) 1(6090,3040) 1(7850,3300) 1(7940,2970) 2(3070,870) 2(3270,830) 2(4260,3040) 2(4380,3210) 2(6060,3040) 2(7880,3300) 2(7910,2970) 3(3100,870) 3(3330,830) 3(4230,3040) 3(4350,3210) 3(6030,3040) 3(7880,2970) 3(7910,3300) 4(3300,870) 4(4320,3210) 4(6090,3070) 4(7850,2980) 4(7940,3300) 5(3330,870) 5(4290,3210) 5(6070,3297.52) 5(6090,3010) 5(7820,2980) 5(7850,3270) 6(3010,810) 6(3160,810) 6(3360,870) 6(4230,3010) 6(6060,3010) 6(6100,3297.52) 6(7790,2980) 6(7880,3270) 7(3130,810) 7(3210,830) 7(4260,3010) 7(4380,3240) 7(6030,3010) 7(6130,3297.52) 7(7790,2950) 7(7910,3270) 8(3100,810) 8(3240,830) 8(4290,3010) 8(4350,3240) 8(6060,3070) 8(6160,3297.52) 8(7820,2950) 8(7940,3270) 9(3070,810) 9(3360,830) 9(4290,2980) 9(4320,3240) 9(6030,3070) 9(6070,3267.52) 9(7850,2950) 9(7850,3240) 10(3040,810) 10(3210,870) 10(4260,2980) 10(4290,3240) 10(6030,2980) 10(6100,3267.52) 10(7880,3240) 11(3010,870) 11(3160,870) 11(3240,870) 11(4230,2980) 11(6060,2980) 11(6130,3267.52) 11(7850,3010) 11(7910,3240) 12(3130,870) 12(4380,3270) 12(6090,2980) 12(6160,3267.52) 12(7850,3040) 12(7940,3240) 13(3210,800) 13(4290,2950) 13(4350,3270) 13(6000,3010) 13(6070,3237.52) 13(7850,3070) 13(7850,3210) 14(3240,800) 14(4260,2950) 14(4320,3270) 14(6000,2980) 14(6100,3237.52) 14(7820,3010) 14(7880,3210) 15(3270,800) 15(4230,2950) 15(4290,3270) 15(6030,2950) 15(6130,3235.79) 15(7820,3040) 15(7910,3210) 16(3010,840) 16(3160,840) 16(3300,800) 16(4290,3300) 16(6060,2950) 16(6160,3235.79) 16(7820,3070) 16(7940,3210) 17(3130,840) 17(3330,800) 17(4290,3070) 17(4320,3300) 17(6070,3207.52) 17(6090,2950) 17(7790,3070) 18(3100,840) 18(3360,800) 18(4230,3070) 18(4260,3070) 18(4350,3300) 18(6000,3040) 18(6100,3207.52) 18(7790,3040) 19(3070,840) 19(4320,2970) 19(4350,2970) 19(4380,3300) 19(6130,3207.52) 19(7790,3010) 20(3040,840) 20(6160,3207.5)
  round 88.19 hole 66.93: 1(7730,2230) 1(8530,2230) 2(6920,2230) 3(6140,2230) 5(5330,2230) 6(4530,2230)
  round 180 hole 100: 1(9070,1550) 2(9070,1250)
  round 100 hole 70: 6(1620,2675)

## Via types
v1: diameter 20, hole 10, Top Layer to Bottom Layer, 116 vias
v2: diameter 30, hole 20, Top Layer to Bottom Layer, 3 vias
v3: diameter 50, hole 30, Top Layer to Bottom Layer, 1 vias

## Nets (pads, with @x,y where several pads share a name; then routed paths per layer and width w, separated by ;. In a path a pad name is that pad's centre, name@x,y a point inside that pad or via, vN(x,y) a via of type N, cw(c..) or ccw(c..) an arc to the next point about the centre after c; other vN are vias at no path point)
3V3: C111.1 C115.1 C118.1 C119.1 C121.1 C123.1 C130.1 C131.1 C132.1 R116.2 R117.1 R125.1 R612.2 U100.8 U101.14 U102.8 U103.5 U104.8 | length 13342.5
  Top Layer w10: v1(2230,540) 2260.75,509.25 2260.75,487.13 2277.87,470 3245,470 3265,450 U101.14@3265,362.99 v1(3265,350) 3265,295 3246.38,276.38 R117.1@3246.38,240 C118.1@3246.38,190 3246.38,132.13 3198.5,132.13 R116.2@3190,123.62 ; U103.5@2887.4,205.87 2906.89,186.38 C131.1@2960,186.38 2960,160 2990,130 3183.62,130 R116.2@3190,123.62 ; R125.1@3190,186.38 R116.2@3190,123.62
  Signal Layer 3 w20: v1(3265,350) 3265,465 3200,530 3040,530 2820,750 2820,1560 2854.25,1594.25 4420,1594.25 ; v1(4567.28,3015) 4563.93,3011.64 4550,3011.64 4550,2980 4420,2850 4420,1594.25 ; 6032.75,1599.25 6032.75,2391.41 6065.51,2424.17 6065.51,2558.98 6065,2559.49 6065,2785 6160,2880 6272.17,2880 6357.28,2965.11 v1(6357.28,3015) ; v1(8127.28,3015) 8095,3015 7625.91,2545.91 7625.91,1607.6 7612.56,1594.25 4420,1594.25
  Bottom Layer w20: R612.2@2185.45,540 v1(2230,540) ; v1(4567.28,3015) C115.1@4623.5,3015 ; C115.1@4636.38,3015 C111.1@4636.38,3060 ; v1(6357.28,3015) 6413.5,3015 C123.1@6426.38,3002.13 ; C121.1@6426.38,3060 C123.1@6426.38,3002.13 ; C123.1@6428.5,3000 C123.1@6426.38,3002.13 ; v1(8127.28,3015) 8202.7,3015 8206.38,3018.68 C130.1@8206.38,3060
3V3a: C615.2 U203.5 U602.1 | length 381.2
  Top Layer w20: C615.2@580,1231.5 586.5,1225 v1(627.01,1225) 675,1225 688.31,1211.69 688.31,1000.16 U203.5@725.87,962.6
5Vout: C40.1 C41.1 C122.1 C133.1 C614.1 L1.2 R118.2 R120.2 U2.1 U2.2 U103.1 U103.3 U203.1 U203.3 | length 3585
  Top Layer w10: U103.3@2806.38,320.35 C133.1@2806.38,370 ; U103.3@2812.6,314.13 2812.6,287.4 2820,280 2880,280 2887.4,287.4 U103.1@2887.4,314.13
  Top Layer w20: C614.1@890,916.38 841.89,916.38 834.13,924.13 U203.1@834.13,962.6 815.94,962.6 796.57,981.96 796.57,1018.04 815.94,1037.4 U203.3@834.13,1037.4 866.73,1070 1260,1070 1300,1110 1300,1160 1321.5,1181.5 v1(1370,1181.5) ; v1(2760,370) C133.1@2806.38,370
  Top Layer w40: v2(1708.5,1320) 1708.5,1384.49 1772.28,1384.49 U2.1@1773.86,1386.06
  Signal Layer 3 w30: v2(1708.5,1320) 2610,1320 2690,1240 2690,862.91 v2(2692.91,860)
  Bottom Layer w20: v1(2760,370) C122.1@2760,590
  Bottom Layer w40: v1(1370,1181.5) 1482.4,1181.5 C40.1@1490.91,1190 1490.91,1300.91 1510,1320 v2(1708.5,1320) ; v2(2692.91,860) R118.2@2692.91,770 2692.91,657.09 C122.1@2760,590
5Vp: C42.1 C600.2 C605.2 J600.48 J600.84 J600.98 J600.112 P1.2 P2.2 P3.2 P4.2 R44.2 U2.4 U600.5 U601.8 | length 11068
  Top Layer w30: U2.4@1573.07,1386.06 1573.07,1508.43 R44.2@1571.5,1510 v1(1580,1510)
  Signal Layer 3 w20: v1(502.24,22.24) v1(722.24,22.24) v1(942.24,22.24) 942.36,22.13 1212.13,22.13 1253.78,63.78 v1(1635.16,63.78) 1800,228.62 v1(1800,765) ; v1(2230,668.5) 2133.5,765 v1(1800,765) ; v1(2717.13,1352.87) 1737.13,1352.87 v1(1580,1510) 1580,960 1775,765 v1(1800,765) ; v1(3176.22,1386.22) 3304.09,1386.22 3330,1412.13 ; P4.2@3430,1380 3362.13,1380 3330,1412.13 ; v1(4670,1510) 4670,1550 ; v1(6270,1510) 6270,1550 ; P3.2@7870,1770 7870,1570 7850,1550 6270,1550 ; 3330,1412.13 3330,1530 3350,1550 4670,1550 ; 4670,1550 6270,1550
  Signal Layer 4 w20: v1(2717.13,1352.87) 2828.77,1352.87 2862.12,1386.22 v1(3176.22,1386.22)
  Bottom Layer w10: U600.5@2230,611.81 v1(2230,668.5)
  Bottom Layer w20: U601.8@1772.72,655 1778.5,660.79 C605.2@1778.5,720 1778.5,758.5 1785,765 v1(1800,765) ; v1(4670,1510) P1.2@4670,1770 ; v1(6270,1510) P2.2@6270,1770
  Bottom Layer w30: C42.1@1530.91,1450 1530.91,1460.91 v1(1580,1510)
5Vs: C616.2 J603.3 U602.16 | length 442.9
  Top Layer w20: J603.3@301.02,991.26 338.74,991.26 350,1002.52 350,1200 v1(330,1220)
  Bottom Layer w20: C616.2@170,1221.5 173.5,1225 U602.16@252.99,1225 257.99,1220 v1(330,1220)
AC_CUR_FAULT: C129.2 J600.64 R125.2 U101.13 | length 2452.9
  Top Layer w10: C129.2@3140,233.62 R125.2@3190,233.62 3215,258.62 v1(3215,362.99)
  Signal Layer 4 w10: v1(1260,20) 3155.5,20 3215,79.5 v1(3215,362.99)
AC_CUR_SENSE: R610.1 U101.12 | length 1253.9
  Top Layer w10: v1(2097.72,600) 2097.72,592.3 2177.14,512.87 2229.47,512.87 2242.87,499.47 2242.87,473.25 2266.13,450 3150,450 3165,435 U101.12@3165,362.99
  Bottom Layer w10: R610.1@2103.62,600 2103.62,613.62 2116.38,613.62
AC_CUR_VREF: C128.1 R604.2 R614.2 U101.10 | length 1435.5
  Top Layer w10: v1(2220,450) 2240,430 3050,430 3065,415 U101.10@3065,362.99 3065,295 3020,250 C128.1@3020,233.62
  Signal Layer 4 w10: v1(2200,151.63) 2200,363.94 2220,383.94 v1(2220,450)
  Bottom Layer w10: R614.2@2185.45,490 2211.04,490 2220,481.04 v1(2220,450)
AC_L: C108.2 C114.1 D100.2 D102.2 L104.3 pad.1@4290,3040 pad.1@6090,3040 pad.1@7940,2970 pad.2@4260,3040 pad.2@6060,3040 pad.2@7910,2970 pad.3@4230,3040 pad.3@6030,3040 pad.3@7880,2970 pad.4@6090,3070 pad.4@7850,2980 pad.5@6090,3010 pad.5@7820,2980 pad.6@4230,3010 pad.6@6060,3010 pad.6@7790,2980 pad.7@4260,3010 pad.7@6030,3010 pad.7@7790,2950 pad.8@4290,3010 pad.8@6060,3070 pad.8@7820,2950 pad.9@4290,2980 pad.9@6030,3070 pad.9@7850,2950 pad.10@4260,2980 pad.10@6030,2980 pad.11@4230,2980 pad.11@6060,2980 pad.11@7850,3010 pad.12@6090,2980 pad.12@7850,3040 pad.13@4290,2950 pad.13@6000,3010 pad.13@7850,3070 pad.14@4260,2950 pad.14@6000,2980 pad.14@7820,3010 pad.15@4230,2950 pad.15@6030,2950 pad.15@7820,3040 pad.16@6060,2950 pad.16@7820,3070 pad.17@4290,3070 pad.17@6090,2950 pad.17@7790,3070 pad.18@4230,3070 pad.18@4260,3070 pad.18@6000,3040 pad.18@7790,3040 pad.19@4320,2970 pad.19@4350,2970 pad.19@7790,3010 U100.1 U100.2 U102.1 U102.2 U104.1 U104.2 | length 1227.6
  Bottom Layer w10: D100.2@3050,1637.24 3050,1780 3150,1880 3150,2000 3210,2060 3274.72,2060 3310,2100 3718.43,2100 D102.2@3868.43,1950
AC_N: D104.2 K1.2 K1.3 pad.1@3040,870 pad.2@3070,870 pad.3@3100,870 pad.6@3010,810 pad.6@3160,810 pad.7@3130,810 pad.8@3100,810 pad.9@3070,810 pad.10@3040,810 pad.11@3010,870 pad.11@3160,870 pad.12@3130,870 pad.16@3010,840 pad.16@3160,840 pad.17@3130,840 pad.18@3100,840 pad.19@3070,840 pad.20@3040,840 RT100.2 RT101.2 U101.5 U101.6 U101.7 U101.8 | length 919.3
  Top Layer w10: K1.2@2238.15,1175.04 2350,1063.19 2350,960 2588.15,721.85 K1.3@2588.15,575.04
  Bottom Layer w10: K1.2@2238.74,1175.63 D104.2@2238.74,1350
ACL_SENSE: C610.1 J600.20 R100.1 R617.2 | length 1960.8
  Signal Layer 4 w10: v1(2079.88,48.9) 2451.02,48.9 2470,67.87 v1(2470,1390)
  Bottom Layer w10: C610.1@2030,166.38 R617.2@2080,166.38 2076.1,162.48 2076.1,52.68 v1(2079.88,48.9) ; v1(2470,1390) R100.1@2540,1390
ACN_SENSE: C609.1 J600.17 R123.1 R616.2 | length 681.2
  Signal Layer 4 w10: v1(2070,830) 2070,358.98 2110,318.98 v1(2110,300)
  Bottom Layer w10: C609.1@2040,366.38 R616.2@2090,366.38 2110,346.38 v1(2110,300) ; v1(2070,830) R123.1@2070,840
ADC_A0: C606.1 J600.24 R607.2 R609.2 | length 1970.6
  Signal Layer 4 w10: v1(2010,70) 2011.77,71.77 2361.77,71.77 2380.75,90.75 2380.75,174.82 2450,244.07 2450,1330 v1(2390,1390)
  Bottom Layer w10: C606.1@1971.5,150 1971.5,88.5 R609.2@1990,70 ; R607.2@2350,1520 2350,1522.13 2390,1482.13 v1(2390,1390)
EARTH0: C107.2 C108.1 C112.1 C113.1 J0.1 pad.6@1620,2675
